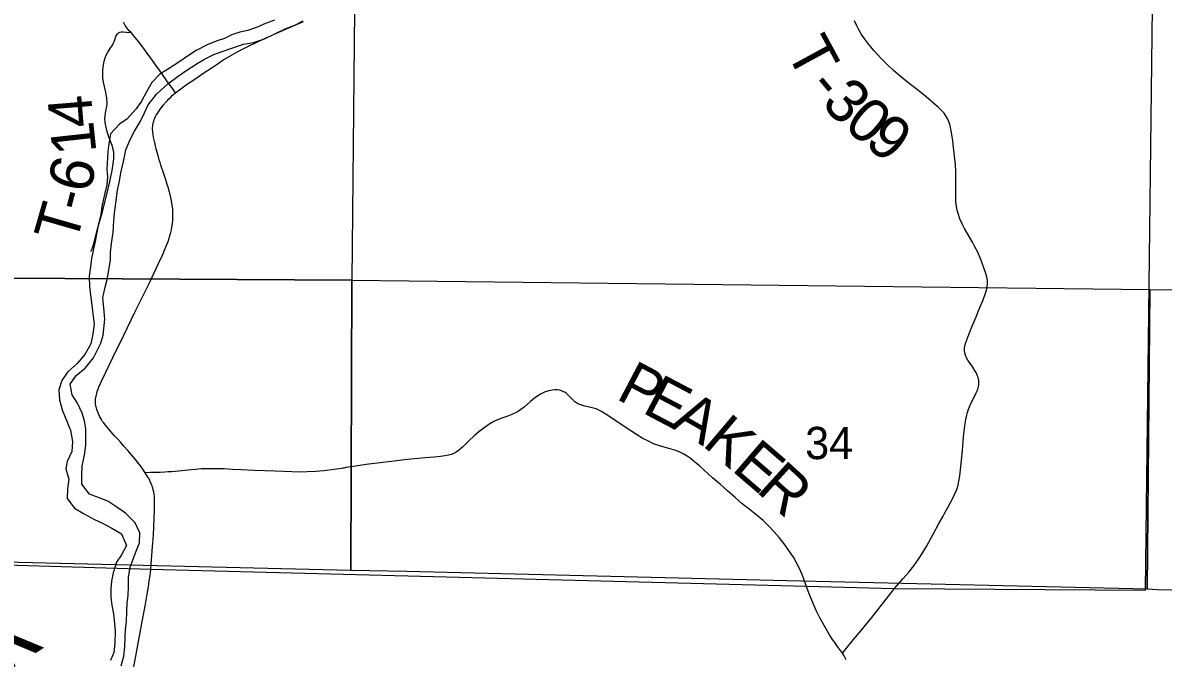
# Model space of a CAD drawing. Extents: x 0 to 34, y 0 to 22.
# Drawn here: x 2.925 to 4.406, y 15.933 to 16.759 of the extents above; entities that cross this region are included whole.
import ezdxf

# ---------------------------------------------------------------- set-up
doc = ezdxf.new("R2010")
doc.units = 0
for name, color, linetype in [('GM_X_Corporation', 7, 'Continuous'), ('GM_X_Major_River', 7, 'Continuous'), ('GM_X_Major_River_Text', 7, 'Continuous'), ('GM_X_Section_Text', 7, 'Continuous'), ('GM_X_State_Route', 7, 'Continuous'), ('GM_X_Township_Road', 7, 'Continuous'), ('GM_X_Township_Road_Text', 7, 'Continuous'), ('GM_X_Township_Text', 7, 'Continuous')]:
    doc.layers.add(name, color=color, linetype=linetype)

msp = doc.modelspace()

# ---------------------------------------------------------------- linework, layer by layer
at = {"layer": 'GM_X_Corporation'}
for points in [[(2.3314, 17.4451), (3.3626, 17.4322), (3.3525, 16.4245), (2.3088, 16.4308)], [(2.3088, 16.4308), (3.3525, 16.4245), (3.3513, 16.0482), (2.4158, 16.0704), (2.3002, 16.073)], [(3.3525, 16.4245), (4.3887, 16.4128), (4.3853, 16.0236), (3.9176, 16.0345), (3.4233, 16.0469), (3.3513, 16.0482)], [(4.3887, 16.4128), (5.4192, 16.4015), (5.4121, 15.9993), (4.3982, 16.023), (4.3853, 16.0236)]]:
    msp.add_lwpolyline(points, close=True, dxfattribs=at)
at = {"layer": 'GM_X_Major_River'}
for points in [[(3.2519, 16.762), (3.2402, 16.7576), (3.2297, 16.7529), (3.2172, 16.7486), (3.207, 16.7466), (3.1968, 16.743), (3.187, 16.7383), (3.1761, 16.7348), (3.1648, 16.7301), (3.1505, 16.7227), (3.1403, 16.7161), (3.1279, 16.7076), (3.1129, 16.6979), (3.1031, 16.6921), (3.0927, 16.6813), (3.086, 16.6691), (3.0793, 16.6568), (3.0723, 16.6469), (3.0603, 16.6335), (3.0506, 16.6273), (3.039, 16.6146), (3.0369, 16.6017), (3.0355, 16.5914), (3.0343, 16.5686), (3.0352, 16.5584), (3.0342, 16.5485), (3.0317, 16.5375), (3.0281, 16.5223), (3.0264, 16.5097), (3.0235, 16.4976), (3.0207, 16.4842), (3.0193, 16.4747), (3.0171, 16.4652), (3.0143, 16.4527), (3.0129, 16.442), (3.0115, 16.4299), (3.0117, 16.4162), (3.0147, 16.3924), (3.016, 16.381), (3.0177, 16.3678), (3.016, 16.3545), (3.0135, 16.3423), (3.0057, 16.3281), (2.9956, 16.3166), (2.9833, 16.3055), (2.9758, 16.2947), (2.9718, 16.2822), (2.9728, 16.2693), (2.9764, 16.2564), (2.9873, 16.23), (2.9898, 16.2153), (2.9888, 16.2024), (2.9826, 16.1894), (2.9812, 16.1799), (2.9848, 16.1667), (2.9831, 16.1541), (2.9828, 16.1416), (2.9925, 16.1288), (3.004, 16.1218), (3.0181, 16.114), (3.0276, 16.11), (3.041, 16.1029), (3.0532, 16.0955), (3.0599, 16.0804), (3.0532, 16.0682), (3.0469, 16.0586), (3.0425, 16.0449), (3.0404, 16.0343), (3.0394, 16.0244), (3.0396, 16.0134), (3.0408, 16.0032), (3.0429, 15.9918), (3.0442, 15.9793), (3.0451, 15.9691), (3.0445, 15.9539), (3.0436, 15.9414), (3.0392, 15.9311)], [(3.0529, 15.9244), (3.0565, 15.937), (3.0575, 15.9488), (3.0581, 15.9617), (3.0587, 15.9716), (3.0597, 15.9814), (3.0603, 15.9951), (3.0609, 16.005), (3.0619, 16.016), (3.0625, 16.0262), (3.0623, 16.0387), (3.0648, 16.0524), (3.0685, 16.0627), (3.0725, 16.073), (3.0769, 16.0837), (3.0771, 16.097), (3.0712, 16.1098), (3.0585, 16.1225), (3.0474, 16.1303), (3.0356, 16.1378), (3.0242, 16.1422), (3.012, 16.1469), (3.0019, 16.1601), (3.0018, 16.1726), (3.0024, 16.1836), (3.0052, 16.1977), (3.0069, 16.2106), (3.0072, 16.2204), (3.007, 16.2318), (3.0054, 16.242), (3.0022, 16.2522), (2.9963, 16.2651), (2.9894, 16.276), (2.9869, 16.2896), (2.9947, 16.3011), (3.006, 16.3107), (3.0171, 16.3241), (3.0264, 16.3428), (3.0296, 16.3535), (3.0316, 16.374), (3.0303, 16.3888), (3.029, 16.4017), (3.0318, 16.4138), (3.0347, 16.4256), (3.0365, 16.4351), (3.0389, 16.4511), (3.0392, 16.4606), (3.0405, 16.4724), (3.0426, 16.4864), (3.0435, 16.5016), (3.0442, 16.5115), (3.0459, 16.5244), (3.0483, 16.5415), (3.0508, 16.5533), (3.0526, 16.5639), (3.0561, 16.5788), (3.059, 16.594), (3.0645, 16.6073), (3.0704, 16.618), (3.0782, 16.631), (3.0833, 16.6417), (3.0878, 16.652), (3.0989, 16.6662), (3.1135, 16.6793), (3.1271, 16.6894), (3.1368, 16.6963), (3.1515, 16.706), (3.1613, 16.7114), (3.1733, 16.7177), (3.1839, 16.7216), (3.1978, 16.726), (3.2118, 16.7311), (3.2247, 16.7332), (3.239, 16.7379), (3.2526, 16.7442), (3.2657, 16.7508), (3.2786, 16.7555)], [(3.2786, 16.7555), (3.2891, 16.761)]]:
    msp.add_lwpolyline(points, dxfattribs=at)
at = {"layer": 'GM_X_State_Route'}
for points in [[(3.0913, 16.0491), (3.092, 16.056), (3.0928, 16.0675), (3.0937, 16.0793), (3.0943, 16.0879), (3.0948, 16.0954), (3.0952, 16.1028), (3.0954, 16.1084), (3.0957, 16.1134), (3.0959, 16.1178), (3.0962, 16.1241), (3.0963, 16.1303), (3.0964, 16.1341), (3.0963, 16.1372), (3.0962, 16.1416), (3.096, 16.1443), (3.0957, 16.1472), (3.0952, 16.1498), (3.0946, 16.1526), (3.094, 16.1546), (3.0936, 16.1561), (3.093, 16.1578), (3.0924, 16.1594), (3.0918, 16.1607), (3.0912, 16.1622), (3.0907, 16.1635), (3.09, 16.165), (3.0893, 16.1664), (3.0887, 16.1676), (3.0877, 16.1692), (3.0864, 16.1712), (3.0841, 16.1749), (3.0812, 16.1794), (3.0781, 16.1837), (3.0746, 16.1883), (3.0715, 16.192), (3.0663, 16.1982), (3.0614, 16.2039), (3.0565, 16.2095), (3.0525, 16.214), (3.0485, 16.2183), (3.0444, 16.2228), (3.0413, 16.2263), (3.039, 16.2288), (3.0348, 16.2338), (3.0324, 16.2367), (3.0303, 16.2394), (3.0288, 16.2414), (3.0274, 16.2437), (3.0262, 16.2459), (3.025, 16.2483), (3.0239, 16.2505), (3.0229, 16.2527), (3.0221, 16.2547), (3.0213, 16.2569), (3.0207, 16.259), (3.0202, 16.2608), (3.0199, 16.2626), (3.0197, 16.2648), (3.0196, 16.2666), (3.0196, 16.2685), (3.0197, 16.2704), (3.02, 16.2727), (3.0203, 16.2744), (3.0207, 16.2761), (3.0212, 16.2781), (3.0219, 16.2803), (3.0226, 16.2824), (3.0233, 16.2844), (3.0239, 16.2861), (3.0247, 16.2878), (3.0274, 16.2937), (3.033, 16.3055), (3.0423, 16.3244), (3.0564, 16.3535), (3.0707, 16.3831), (3.079, 16.3998), (3.0891, 16.4205), (3.1016, 16.4462), (3.1065, 16.457), (3.1084, 16.4614), (3.1102, 16.4656), (3.1124, 16.4708), (3.114, 16.475), (3.1153, 16.479), (3.1163, 16.4826), (3.1174, 16.4864), (3.1182, 16.4899), (3.1189, 16.4937), (3.1195, 16.4977), (3.12, 16.5029), (3.1202, 16.5079), (3.1201, 16.513), (3.12, 16.5163), (3.1196, 16.5202), (3.1189, 16.5242), (3.1183, 16.5282), (3.1175, 16.5318), (3.1165, 16.5358), (3.1154, 16.5403), (3.1142, 16.5442), (3.1128, 16.5489), (3.1109, 16.5547), (3.1095, 16.5588), (3.1069, 16.5665), (3.1057, 16.5702), (3.1045, 16.5738), (3.1035, 16.5774), (3.1024, 16.581), (3.1013, 16.5847), (3.1001, 16.5889), (3.0993, 16.592), (3.0985, 16.5949), (3.0977, 16.5984), (3.097, 16.6014), (3.0964, 16.604), (3.0958, 16.6068), (3.0951, 16.6104), (3.0945, 16.6136), (3.0941, 16.6161), (3.0939, 16.6184), (3.0937, 16.6204), (3.0938, 16.6226), (3.0939, 16.6245), (3.0942, 16.6263), (3.0945, 16.6284), (3.0952, 16.6309), (3.0958, 16.633), (3.0966, 16.6351), (3.0975, 16.6369), (3.0985, 16.6386), (3.1, 16.641), (3.1014, 16.6432), (3.1039, 16.6468), (3.1076, 16.6516), (3.1112, 16.6559), (3.113, 16.6579), (3.1149, 16.66), (3.1172, 16.6623), (3.1192, 16.6643), (3.1215, 16.6661), (3.1235, 16.6678), (3.1256, 16.6694), (3.1287, 16.6718), (3.1321, 16.6744), (3.1358, 16.677), (3.1392, 16.6794), (3.1459, 16.6839), (3.1531, 16.6887), (3.1603, 16.6936), (3.1711, 16.7008), (3.1763, 16.7042), (3.1851, 16.71), (3.1962, 16.7168), (3.2053, 16.7219), (3.2164, 16.7276), (3.2309, 16.7345), (3.2548, 16.745), (3.2895, 16.7602)], [(3.0692, 15.923), (3.0729, 15.9418), (3.0803, 15.9816), (3.0831, 15.9973), (3.0854, 16.0093), (3.0868, 16.0172), (3.0885, 16.0268), (3.0894, 16.0344), (3.0904, 16.0415), (3.0913, 16.0491)]]:
    msp.add_lwpolyline(points, dxfattribs=at)
at = {"layer": 'GM_X_Township_Road'}
for points in [[(3.0659, 16.7459), (3.0635, 16.7484), (3.0607, 16.7517), (3.0582, 16.7553), (3.0558, 16.7596)], [(4.0567, 16.0241), (4.0598, 16.0278), (4.068, 16.037), (4.0756, 16.0459), (4.0822, 16.0541), (4.0883, 16.0626), (4.0941, 16.0714), (4.0991, 16.08), (4.1073, 16.0953), (4.1147, 16.1089), (4.1202, 16.1186), (4.1229, 16.1235), (4.1265, 16.1299), (4.1323, 16.1408), (4.1355, 16.1475), (4.1379, 16.1533), (4.1396, 16.1586), (4.1408, 16.164), (4.1419, 16.1708), (4.1437, 16.1868), (4.1452, 16.2039), (4.1468, 16.2208), (4.1476, 16.2286), (4.1485, 16.2359), (4.1493, 16.2409), (4.1499, 16.2448), (4.1504, 16.2472), (4.151, 16.2497), (4.1516, 16.2521), (4.1524, 16.2544), (4.1534, 16.2572), (4.1546, 16.2602), (4.156, 16.2636), (4.1576, 16.267), (4.1633, 16.2785), (4.1644, 16.2811), (4.1651, 16.2831), (4.1657, 16.2849), (4.1661, 16.2867), (4.1664, 16.2886), (4.1665, 16.2903), (4.1666, 16.2919), (4.1665, 16.2934), (4.1664, 16.295), (4.1661, 16.2965), (4.1658, 16.298), (4.1654, 16.2995), (4.1646, 16.3015), (4.164, 16.3029), (4.1631, 16.3047), (4.162, 16.3067), (4.1587, 16.3119), (4.1524, 16.3209), (4.1506, 16.3241), (4.1492, 16.3275), (4.1484, 16.3305), (4.148, 16.3335), (4.148, 16.3366), (4.1485, 16.3396), (4.1498, 16.3438), (4.1536, 16.3543), (4.1585, 16.3662), (4.163, 16.3772), (4.1668, 16.3864), (4.1722, 16.399), (4.175, 16.4065), (4.1766, 16.4119), (4.1775, 16.4162), (4.1779, 16.4205), (4.1777, 16.4242), (4.1771, 16.4285), (4.1758, 16.4333), (4.1733, 16.4409), (4.1693, 16.4513), (4.1652, 16.4609), (4.1616, 16.4681), (4.1584, 16.4741), (4.148, 16.4918), (4.1448, 16.4979), (4.1421, 16.5041), (4.14, 16.51), (4.1385, 16.5154), (4.1376, 16.5203), (4.1369, 16.5264), (4.1366, 16.5339), (4.1368, 16.5475), (4.1367, 16.5655), (4.1362, 16.5742), (4.1355, 16.5822), (4.1339, 16.597), (4.1328, 16.6057), (4.1308, 16.6186), (4.1294, 16.6252), (4.1281, 16.6294), (4.1264, 16.6334), (4.1243, 16.6372), (4.1214, 16.6412), (4.1182, 16.645), (4.1142, 16.6489), (4.0981, 16.6624), (4.089, 16.6699), (4.0741, 16.6818), (4.0643, 16.6895), (4.0558, 16.6967), (4.0477, 16.7044), (4.0394, 16.7128), (4.0307, 16.7224), (4.0239, 16.7305), (4.0186, 16.7373), (4.0144, 16.7435), (4.0109, 16.7493), (4.0078, 16.7554), (4.0053, 16.7611)], [(3.0137, 16.4617), (3.015, 16.4646), (3.0163, 16.4681), (3.018, 16.474), (3.0228, 16.4927), (3.0281, 16.5119), (3.0331, 16.5305), (3.0383, 16.5529), (3.0412, 16.5669), (3.0427, 16.5755), (3.0434, 16.5823), (3.0435, 16.5866), (3.0432, 16.5903), (3.0424, 16.5946), (3.0411, 16.5994), (3.0373, 16.6093), (3.0359, 16.6134), (3.0344, 16.6188), (3.033, 16.6248), (3.0323, 16.6297), (3.0319, 16.6341), (3.032, 16.6378), (3.0324, 16.6415), (3.0337, 16.6482), (3.0346, 16.6531), (3.0347, 16.6562), (3.0344, 16.6586), (3.0341, 16.6611), (3.0324, 16.6702), (3.03, 16.6818), (3.0293, 16.6873), (3.0291, 16.6923), (3.0293, 16.6978), (3.03, 16.704), (3.031, 16.7089), (3.0322, 16.7131), (3.0336, 16.7165), (3.0356, 16.7204), (3.0387, 16.7251), (3.0417, 16.7298), (3.043, 16.7326), (3.0443, 16.7354), (3.0461, 16.7407), (3.0471, 16.7429), (3.0482, 16.7444), (3.0496, 16.7456), (3.0513, 16.7464), (3.0531, 16.7468), (3.0556, 16.7469), (3.0593, 16.7465), (3.0659, 16.7459)], [(3.1235, 16.6678), (3.1198, 16.673), (3.1133, 16.682), (3.1065, 16.6916), (3.1025, 16.6971), (3.098, 16.7038), (3.0914, 16.7128), (3.0784, 16.7303), (3.0659, 16.7459)], [(3.943, 16.0269), (3.9416, 16.0307), (3.937, 16.0429), (3.9333, 16.0515), (3.9296, 16.0586), (3.9258, 16.0651), (3.9207, 16.0728), (3.9138, 16.0824), (3.9073, 16.0907), (3.9008, 16.0982), (3.8936, 16.1058), (3.8864, 16.1127), (3.8794, 16.1189), (3.8682, 16.1277), (3.8595, 16.1346), (3.85, 16.1426), (3.8403, 16.1514), (3.831, 16.1594), (3.8207, 16.1683), (3.8037, 16.1837), (3.798, 16.1886), (3.7918, 16.1937), (3.7877, 16.1965), (3.7834, 16.199), (3.7784, 16.2015), (3.7732, 16.2035), (3.7673, 16.2053), (3.7578, 16.208), (3.7507, 16.2101), (3.7443, 16.2125), (3.7375, 16.2157), (3.7304, 16.2194), (3.7219, 16.2246), (3.7073, 16.234), (3.6912, 16.2446), (3.6815, 16.2513), (3.6768, 16.2543), (3.673, 16.2562), (3.6695, 16.2576), (3.6647, 16.259), (3.655, 16.2612), (3.6509, 16.2623), (3.6474, 16.2637), (3.6446, 16.2651), (3.6421, 16.2668), (3.6393, 16.2693), (3.6341, 16.2746), (3.631, 16.2777), (3.629, 16.2792), (3.6274, 16.28), (3.6246, 16.2811), (3.6223, 16.2819), (3.6192, 16.2824), (3.6161, 16.2825), (3.6124, 16.2821), (3.6082, 16.2812), (3.6034, 16.2796), (3.5984, 16.2773), (3.5941, 16.2748), (3.5895, 16.2716), (3.5843, 16.2671), (3.5764, 16.2601), (3.572, 16.2567), (3.5684, 16.2543), (3.5651, 16.2525), (3.56, 16.2502), (3.5536, 16.2478), (3.5473, 16.2455), (3.5415, 16.2433), (3.537, 16.2412), (3.5316, 16.2381), (3.5243, 16.2333), (3.5174, 16.2281), (3.5112, 16.2228), (3.5041, 16.2159), (3.4961, 16.2081), (3.4909, 16.2038), (3.4881, 16.2017), (3.4849, 16.1998), (3.4815, 16.1984), (3.4779, 16.1975), (3.473, 16.1966), (3.4675, 16.1958), (3.4594, 16.195), (3.4483, 16.1941), (3.4242, 16.1918), (3.4038, 16.1896), (3.389, 16.1878), (3.3712, 16.1854), (3.357, 16.1835), (3.3516, 16.1826), (3.3478, 16.1821), (3.3461, 16.1817), (3.3448, 16.1815), (3.3426, 16.1809), (3.3408, 16.1806), (3.3392, 16.1803), (3.3296, 16.1789), (3.316, 16.1774), (3.3055, 16.1765), (3.2943, 16.1759), (3.2844, 16.1757), (3.2745, 16.176), (3.2529, 16.1769), (3.2256, 16.1776), (3.2088, 16.1785), (3.1977, 16.1791), (3.1865, 16.1797), (3.1778, 16.1799), (3.1648, 16.1799), (3.1598, 16.1799), (3.1567, 16.1797), (3.1493, 16.1792), (3.1436, 16.1786), (3.1359, 16.1777), (3.1278, 16.1769), (3.123, 16.1766), (3.1182, 16.1762), (3.114, 16.1759), (3.1096, 16.1757), (3.1034, 16.1753), (3.0978, 16.1752), (3.0911, 16.175), (3.0841, 16.1749)], [(3.9894, 15.9409), (3.9885, 15.9423), (3.9832, 15.9492), (3.9803, 15.9532), (3.9782, 15.9563), (3.9768, 15.9583), (3.9728, 15.9646), (3.9674, 15.9736), (3.9602, 15.9867), (3.9554, 15.9961), (3.9513, 16.0052), (3.9467, 16.0167), (3.943, 16.0269)], [(3.9894, 15.9409), (3.9948, 15.9473), (4.004, 15.9583), (4.0139, 15.9701), (4.0276, 15.9869), (4.0539, 16.0207), (4.0567, 16.0241)], [(3.9943, 15.932), (3.9911, 15.9381), (3.9894, 15.9409)]]:
    msp.add_lwpolyline(points, dxfattribs=at)
at = {"layer": 'GM_X_Township_Text'}
msp.add_lwpolyline([(2.1, 19.4241), (2.1, 16.074), (2.3294, 16.0685), (2.5414, 16.0663), (3.0911, 16.0497), (3.9428, 16.0275), (4.0565, 16.0246), (4.383, 16.0223), (4.3994, 17.3911), (4.4004, 17.4134)], dxfattribs=at)

# ---------------------------------------------------------------- texts
at = {"layer": 'GM_X_Major_River_Text'}
msp.add_text('Fork', height=0.0947, rotation=32.9054, dxfattribs=at).set_placement((2.7401, 15.8102))
at = {"layer": 'GM_X_Section_Text'}
msp.add_text('34', height=0.04186, rotation=0, dxfattribs=at).set_placement((3.9411, 16.1925))
at = {"layer": 'GM_X_Township_Road_Text'}
for s, rotation, p in [('T', 298.5126, (3.9153, 16.7217)), ('-', 310.1844, (3.9427, 16.674)), ('3', 314.2996, (3.9607, 16.6529)), ('4', 94.6626, (3.0172, 16.6245)), ('0', 319.8162, (3.9895, 16.6238)), ('9', 321.2792, (4.0165, 16.6009)), ('1', 96.2779, (3.021, 16.5904)), ('6', 77.2043, (3.0121, 16.536)), ('T', 73.9521, (2.9936, 16.4695)), ('-', 75.2058, (3.0057, 16.5115)), ('P', 332.2959, (3.694, 16.2714)), ('E', 332.2943, (3.7279, 16.2536)), ('A', 330.2777, (3.7651, 16.2341)), ('K', 319.7579, (3.8062, 16.2109)), ('E', 319.3132, (3.8443, 16.1787)), ('R', 317.7775, (3.8762, 16.1512))]:
    msp.add_text(s, height=0.0568, rotation=rotation, dxfattribs=at).set_placement(p)

doc.saveas('drawing.dxf')
